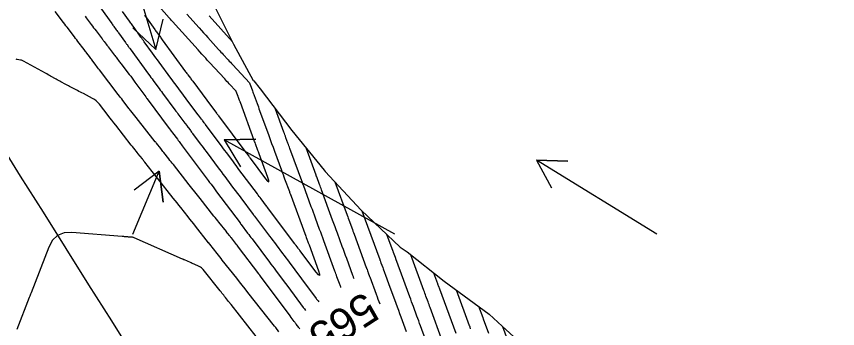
# Model space of a CAD drawing. Extents: x 954385 to 988206, y 1868364 to 1924553.
# Drawn here: x 957284.9 to 957441.7, y 1920650.9 to 1920710.5 of the extents above; entities that cross this region are included whole.
import ezdxf

# ---------------------------------------------------------------- set-up
doc = ezdxf.new("R2010")
doc.units = 0
for name, color, linetype in [('Default', 7, 'Continuous'), ('Ex_Contour Labels', 7, 'Continuous'), ('Ex_Major Contours', 7, 'Continuous'), ('Ex_Minor Contours', 7, 'Continuous'), ('Perimeter', 7, 'Continuous'), ('Slopes', 7, 'Continuous')]:
    doc.layers.add(name, color=color, linetype=linetype)

msp = doc.modelspace()

# ---------------------------------------------------------------- linework, layer by layer
at = {"layer": 'Default'}
msp.add_arc((966995.78, 1926764.93), 11459.16, 211.460692, 214.075074, dxfattribs=at)
at = {"layer": 'Ex_Major Contours'}
for points in [[(957300.93, 1920712.2), (957303.09, 1920709.21), (957303.2, 1920709.06), (957303.31, 1920708.9), (957303.42, 1920708.75), (957303.53, 1920708.6), (957303.97, 1920707.99), (957304.08, 1920707.84), (957304.19, 1920707.69), (957304.3, 1920707.53), (957304.41, 1920707.38), (957305.73, 1920705.56), (957305.8, 1920705.46), (957305.87, 1920705.36), (957305.94, 1920705.25), (957306.02, 1920705.15), (957306.31, 1920704.75), (957306.38, 1920704.65), (957306.45, 1920704.55), (957306.53, 1920704.45), (957306.6, 1920704.35), (957310.14, 1920699.5), (957310.36, 1920699.19), (957310.58, 1920698.89), (957310.8, 1920698.59), (957311.02, 1920698.29), (957311.91, 1920697.08), (957312.13, 1920696.78), (957312.35, 1920696.48), (957312.57, 1920696.18), (957312.79, 1920695.88), (957315.17, 1920692.69), (957315.36, 1920692.43), (957315.56, 1920692.18), (957315.75, 1920691.92), (957315.94, 1920691.66), (957317.08, 1920690.14), (957317.09, 1920690.12), (957317.12, 1920690.08), (957317.13, 1920690.07), (957317.42, 1920689.68), (957317.47, 1920689.62), (957317.52, 1920689.55), (957317.57, 1920689.48), (957317.62, 1920689.42), (957318.13, 1920688.73), (957318.23, 1920688.6), (957318.33, 1920688.46), (957318.43, 1920688.32), (957318.54, 1920688.19), (957320, 1920686.22), (957320.28, 1920685.85), (957320.56, 1920685.48), (957320.84, 1920685.1), (957321.11, 1920684.73), (957323.63, 1920681.36), (957323.98, 1920680.9), (957324.32, 1920680.44), (957324.66, 1920679.99), (957325, 1920679.53), (957326.37, 1920677.7), (957326.71, 1920677.25), (957327.05, 1920676.79), (957327.4, 1920676.33), (957327.74, 1920675.88), (957330.11, 1920672.7), (957330.14, 1920672.67), (957330.16, 1920672.64), (957330.21, 1920672.58), (957330.23, 1920672.55), (957330.25, 1920672.52), (957330.32, 1920672.44), (957330.34, 1920672.41), (957333.22, 1920668.57), (957333.53, 1920668.16), (957333.84, 1920667.75), (957334.15, 1920667.33), (957334.46, 1920666.92), (957335.7, 1920665.26), (957336.01, 1920664.85), (957336.32, 1920664.44), (957336.63, 1920664.02), (957336.94, 1920663.61), (957340.4, 1920658.98), (957341.04, 1920658.13), (957342.14, 1920656.65), (957342.22, 1920656.54), (957342.31, 1920656.43), (957342.39, 1920656.32), (957342.48, 1920656.2), (957342.61, 1920656.03)], [(957326.15, 1920705.7), (957321.7, 1920710.64)], [(957346.85, 1920658.78), (957346.81, 1920658.9), (957346.75, 1920659.05), (957346.69, 1920659.2), (957346.64, 1920659.35), (957346.58, 1920659.51), (957346.1, 1920660.82), (957346, 1920661.09), (957345.91, 1920661.36), (957345.81, 1920661.63), (957345.71, 1920661.9), (957343.59, 1920667.69), (957343.39, 1920668.23), (957343.19, 1920668.78), (957342.99, 1920669.32), (957342.79, 1920669.86), (957341.99, 1920672.02), (957341.8, 1920672.57), (957341.6, 1920673.11), (957341.4, 1920673.65), (957341.2, 1920674.19), (957339.69, 1920678.3), (957339.66, 1920678.35), (957339.62, 1920678.47), (957339.6, 1920678.52), (957339.57, 1920678.6), (957339.56, 1920678.65), (957337.11, 1920685.31), (957337.02, 1920685.57), (957336.92, 1920685.83), (957336.83, 1920686.09), (957336.73, 1920686.35), (957336.35, 1920687.38), (957336.26, 1920687.64), (957336.16, 1920687.9), (957336.07, 1920688.15), (957335.97, 1920688.41), (957334.36, 1920692.85)], [(957366.27, 1920648.44), (957363.88, 1920654.94), (957363.78, 1920655.22), (957363.68, 1920655.49), (957363.58, 1920655.76), (957363.48, 1920656.03), (957363.08, 1920657.12), (957362.98, 1920657.39), (957362.88, 1920657.67), (957362.78, 1920657.94), (957362.68, 1920658.21), (957360.18, 1920665.02)]]:
    msp.add_lwpolyline(points, dxfattribs=at)
at = {"layer": 'Ex_Minor Contours'}
for points in [[(957309.36, 1920710.74), (957309.54, 1920710.5), (957309.63, 1920710.37), (957309.72, 1920710.25), (957311.3, 1920708.06), (957311.42, 1920707.9), (957311.54, 1920707.73), (957311.66, 1920707.57), (957311.78, 1920707.4), (957312.26, 1920706.75), (957312.38, 1920706.58), (957312.5, 1920706.42), (957312.62, 1920706.25), (957312.74, 1920706.09), (957317.21, 1920699.97), (957317.32, 1920699.81), (957317.43, 1920699.66), (957317.54, 1920699.51), (957317.65, 1920699.36), (957318.11, 1920698.76), (957318.22, 1920698.6), (957318.33, 1920698.45), (957318.44, 1920698.3), (957318.56, 1920698.15), (957322.16, 1920693.32), (957322.18, 1920693.3), (957323.12, 1920692.05), (957323.18, 1920691.97), (957323.24, 1920691.89), (957323.36, 1920691.73), (957323.42, 1920691.65), (957323.47, 1920691.57), (957328.72, 1920684.54), (957328.86, 1920684.36), (957328.99, 1920684.18), (957329.26, 1920683.82), (957329.33, 1920683.73), (957329.39, 1920683.64), (957329.46, 1920683.55), (957329.53, 1920683.46), (957332.45, 1920679.55), (957332.86, 1920679.06), (957333.07, 1920678.93), (957333.08, 1920679.18), (957332.89, 1920679.79), (957331.24, 1920684.27), (957331.17, 1920684.48), (957331.09, 1920684.7), (957331.01, 1920684.92), (957330.93, 1920685.13), (957330.61, 1920686), (957330.53, 1920686.22), (957330.45, 1920686.43), (957330.37, 1920686.65), (957330.3, 1920686.87), (957327.66, 1920694.08), (957327.63, 1920694.18), (957327.59, 1920694.27), (957327.56, 1920694.37), (957327.52, 1920694.47), (957327.37, 1920694.85), (957327.34, 1920694.95), (957327.3, 1920695.04), (957327.26, 1920695.14), (957327.23, 1920695.24), (957326.87, 1920696.2), (957326.87, 1920696.21), (957326.87, 1920696.21), (957326.87, 1920696.22), (957326.86, 1920696.22), (957326.84, 1920696.24), (957326.83, 1920696.26), (957325.53, 1920697.66), (957325.32, 1920697.9), (957325.1, 1920698.13), (957324.88, 1920698.37), (957324.67, 1920698.6), (957321.77, 1920701.75), (957321.58, 1920701.95), (957321.4, 1920702.15), (957321.22, 1920702.35), (957321.04, 1920702.55), (957320.31, 1920703.36), (957319.94, 1920703.76), (957319.58, 1920704.17), (957314.73, 1920709.54), (957314.68, 1920709.6), (957314.62, 1920709.66), (957314.57, 1920709.72), (957314.52, 1920709.78), (957314.31, 1920710.02), (957314.2, 1920710.14), (957314.09, 1920710.25), (957312.15, 1920712.43)], [(957339.01, 1920650.86), (957338.9, 1920651.01), (957338.79, 1920651.15), (957338.33, 1920651.77), (957338.23, 1920651.9), (957338.13, 1920652.03), (957338.04, 1920652.16), (957337.94, 1920652.28), (957337.38, 1920653.03), (957337.25, 1920653.2), (957337.21, 1920653.26), (957331.62, 1920660.74), (957331.34, 1920661.11), (957331.29, 1920661.17), (957331.25, 1920661.23), (957331.2, 1920661.3), (957331.15, 1920661.36), (957327.32, 1920666.47), (957327.17, 1920666.67), (957327.02, 1920666.86), (957326.87, 1920667.06), (957326.71, 1920667.25), (957325.94, 1920668.23), (957325.86, 1920668.32), (957325.79, 1920668.42), (957325.71, 1920668.52), (957325.63, 1920668.61), (957325.21, 1920669.15), (957325.15, 1920669.22), (957325.02, 1920669.39), (957324.98, 1920669.44), (957323.57, 1920671.22), (957323.33, 1920671.52), (957323.09, 1920671.82), (957322.86, 1920672.12), (957322.62, 1920672.42), (957319.98, 1920675.75), (957319.46, 1920676.41), (957318.94, 1920677.06), (957318.42, 1920677.72), (957317.91, 1920678.37), (957314.86, 1920682.24), (957314.65, 1920682.51), (957314.43, 1920682.78), (957314.22, 1920683.05), (957314.01, 1920683.32), (957313.02, 1920684.58), (957312.87, 1920684.76), (957312.73, 1920684.94), (957312.59, 1920685.12), (957312.45, 1920685.3), (957311.62, 1920686.35), (957311.57, 1920686.42), (957311.49, 1920686.52), (957311.48, 1920686.52), (957311.45, 1920686.57), (957311.43, 1920686.58), (957311.42, 1920686.6), (957307.78, 1920691.21), (957307.52, 1920691.53), (957307.27, 1920691.85), (957306.76, 1920692.5), (957306.64, 1920692.66), (957306.51, 1920692.82), (957306.39, 1920692.98), (957306.26, 1920693.14), (957305.22, 1920694.5), (957305.01, 1920694.78), (957304.79, 1920695.06), (957304.58, 1920695.34), (957304.36, 1920695.62), (957300.75, 1920700.34), (957300.58, 1920700.56), (957300.41, 1920700.78), (957300.25, 1920700.99), (957300.08, 1920701.21), (957299.34, 1920702.2), (957299.21, 1920702.36), (957299.08, 1920702.53), (957298.96, 1920702.7), (957298.83, 1920702.86), (957298.33, 1920703.53), (957298.2, 1920703.7), (957298.07, 1920703.87), (957297.95, 1920704.03), (957297.82, 1920704.2), (957296.66, 1920705.73), (957296.44, 1920706.04), (957296.21, 1920706.34), (957295.98, 1920706.64), (957295.75, 1920706.95), (957294.83, 1920708.16), (957294.6, 1920708.46), (957294.37, 1920708.77), (957294.14, 1920709.07), (957293.91, 1920709.37), (957292.31, 1920711.48)], [(957298, 1920710.57), (957298.23, 1920710.26), (957299.19, 1920708.99), (957299.42, 1920708.69), (957299.65, 1920708.39), (957299.88, 1920708.09), (957300.1, 1920707.79), (957301.27, 1920706.24), (957301.37, 1920706.12), (957301.47, 1920705.99), (957301.56, 1920705.86), (957301.66, 1920705.73), (957302.05, 1920705.21), (957302.15, 1920705.08), (957302.25, 1920704.96), (957302.34, 1920704.83), (957302.44, 1920704.7), (957303.56, 1920703.21), (957303.68, 1920703.05), (957303.8, 1920702.9), (957303.93, 1920702.74), (957304.05, 1920702.58), (957304.53, 1920701.95), (957304.65, 1920701.79), (957304.77, 1920701.63), (957304.89, 1920701.47), (957305.02, 1920701.31), (957306.44, 1920699.46), (957306.72, 1920699.1), (957306.99, 1920698.73), (957307.26, 1920698.36), (957307.53, 1920698), (957309.58, 1920695.19), (957309.67, 1920695.07), (957309.76, 1920694.94), (957309.78, 1920694.91), (957309.81, 1920694.88), (957309.83, 1920694.85), (957309.85, 1920694.82), (957314.07, 1920689.16), (957314.17, 1920689.04), (957314.26, 1920688.91), (957314.53, 1920688.55), (957314.55, 1920688.53), (957314.58, 1920688.48), (957314.6, 1920688.46), (957314.69, 1920688.34), (957314.71, 1920688.31), (957315.64, 1920687.07), (957315.72, 1920686.97), (957315.79, 1920686.86), (957315.87, 1920686.76), (957315.95, 1920686.66), (957316.25, 1920686.24), (957316.41, 1920686.04), (957316.56, 1920685.83), (957321.51, 1920679.21), (957321.64, 1920679.03), (957321.78, 1920678.85), (957321.91, 1920678.67), (957322.05, 1920678.49), (957322.59, 1920677.77), (957322.72, 1920677.59), (957322.86, 1920677.41), (957322.99, 1920677.23), (957323.13, 1920677.05), (957327.59, 1920671.09), (957327.61, 1920671.06), (957327.64, 1920671.02), (957327.65, 1920671), (957327.76, 1920670.86), (957327.81, 1920670.79), (957329.04, 1920669.15), (957329.25, 1920668.87), (957329.46, 1920668.59), (957329.68, 1920668.31), (957329.89, 1920668.03), (957333.2, 1920663.61), (957333.49, 1920663.22), (957333.78, 1920662.83), (957334.08, 1920662.45), (957334.37, 1920662.06), (957335.82, 1920660.11), (957336.7, 1920658.94), (957339.67, 1920654.96), (957339.72, 1920654.89), (957339.77, 1920654.82), (957339.82, 1920654.76), (957339.87, 1920654.69), (957340.1, 1920654.39)], [(957317.45, 1920710.94), (957319.79, 1920708.34), (957320.21, 1920707.88), (957320.62, 1920707.42), (957321.04, 1920706.96), (957321.45, 1920706.5), (957323.49, 1920704.24), (957323.72, 1920703.99), (957323.94, 1920703.74), (957324.17, 1920703.5), (957324.39, 1920703.25), (957325.3, 1920702.27), (957325.52, 1920702.02), (957325.75, 1920701.78), (957325.98, 1920701.53), (957326.2, 1920701.29), (957329.38, 1920697.85), (957329.38, 1920697.84), (957329.39, 1920697.83), (957329.46, 1920697.64), (957329.47, 1920697.61), (957329.48, 1920697.57), (957329.49, 1920697.54), (957329.51, 1920697.51), (957329.97, 1920696.3), (957330.05, 1920696.08), (957330.13, 1920695.87), (957330.21, 1920695.65), (957330.29, 1920695.44), (957330.85, 1920693.9), (957330.97, 1920693.57), (957331.09, 1920693.24), (957331.21, 1920692.91), (957331.33, 1920692.58), (957333.08, 1920687.79), (957333.35, 1920687.04), (957333.63, 1920686.3), (957333.9, 1920685.55), (957334.17, 1920684.81), (957335.5, 1920681.18), (957335.66, 1920680.76), (957335.81, 1920680.35), (957335.96, 1920679.93), (957336.11, 1920679.52), (957337.01, 1920677.07), (957337.03, 1920677.02), (957337.05, 1920676.96), (957337.1, 1920676.81), (957337.11, 1920676.79), (957337.14, 1920676.72), (957340.13, 1920668.59), (957340.24, 1920668.31), (957340.34, 1920668.02), (957340.55, 1920667.46), (957340.6, 1920667.31), (957340.65, 1920667.17), (957340.7, 1920667.03), (957340.76, 1920666.89), (957342.57, 1920661.94), (957342.77, 1920661.29), (957342.77, 1920661.03), (957342.54, 1920661.16), (957342.11, 1920661.69), (957339.02, 1920665.82), (957338.94, 1920665.93), (957338.86, 1920666.04), (957338.78, 1920666.15), (957338.69, 1920666.26), (957338.29, 1920666.8), (957338.13, 1920667.01), (957338.05, 1920667.12), (957332.86, 1920674.02), (957332.82, 1920674.08), (957332.8, 1920674.1), (957332.71, 1920674.23), (957332.69, 1920674.25), (957332.68, 1920674.27), (957332.66, 1920674.3), (957332.64, 1920674.32), (957331.61, 1920675.7), (957331.43, 1920675.94), (957331.25, 1920676.17), (957331.07, 1920676.41), (957330.9, 1920676.65), (957327.39, 1920681.32), (957327.12, 1920681.68), (957326.86, 1920682.04), (957326.59, 1920682.4), (957326.32, 1920682.76), (957325.25, 1920684.2), (957324.98, 1920684.56), (957324.71, 1920684.92), (957324.44, 1920685.28), (957324.17, 1920685.64), (957321.01, 1920689.88), (957320.94, 1920689.97), (957320.87, 1920690.06), (957320.81, 1920690.14), (957320.74, 1920690.23), (957320.48, 1920690.58), (957320.41, 1920690.67), (957320.35, 1920690.76), (957320.28, 1920690.85), (957320.22, 1920690.93), (957319.65, 1920691.69), (957319.64, 1920691.7), (957319.62, 1920691.73), (957317.46, 1920694.63), (957317.2, 1920694.97), (957316.94, 1920695.32), (957316.69, 1920695.66), (957316.43, 1920696), (957315.4, 1920697.38), (957315.15, 1920697.72), (957314.89, 1920698.07), (957314.64, 1920698.42), (957314.38, 1920698.76), (957312.18, 1920701.78), (957311.86, 1920702.22), (957311.54, 1920702.65), (957311.22, 1920703.09), (957310.91, 1920703.53), (957309.31, 1920705.71), (957309.15, 1920705.93), (957309, 1920706.14), (957308.84, 1920706.36), (957308.68, 1920706.57), (957308.01, 1920707.51), (957307.88, 1920707.69), (957307.75, 1920707.86), (957307.62, 1920708.04), (957307.5, 1920708.22), (957306.99, 1920708.92), (957306.86, 1920709.1), (957306.73, 1920709.28), (957306.6, 1920709.45), (957306.48, 1920709.63), (957305.14, 1920711.48)], [(957335.03, 1920650.32), (957334.4, 1920651.12), (957334.24, 1920651.32), (957334.2, 1920651.37), (957329.1, 1920657.84), (957328.56, 1920658.52), (957328.02, 1920659.2), (957327.49, 1920659.88), (957326.95, 1920660.55), (957324.21, 1920664.01), (957323.97, 1920664.31), (957323.73, 1920664.62), (957323.49, 1920664.92), (957323.24, 1920665.23), (957321.82, 1920667.03), (957321.76, 1920667.1), (957321.61, 1920667.28), (957321.59, 1920667.32), (957319.11, 1920670.45), (957318.75, 1920670.9), (957318.4, 1920671.34), (957318.04, 1920671.79), (957317.69, 1920672.24), (957316.27, 1920674.03), (957315.91, 1920674.48), (957315.56, 1920674.93), (957315.2, 1920675.38), (957314.85, 1920675.83), (957311.84, 1920679.64), (957311.59, 1920679.96), (957311.34, 1920680.28), (957311.09, 1920680.59), (957310.84, 1920680.91), (957309.42, 1920682.71), (957309.38, 1920682.76), (957309.34, 1920682.81), (957309.3, 1920682.86), (957309.26, 1920682.91), (957309.07, 1920683.16), (957308.99, 1920683.26), (957308.95, 1920683.31), (957308.11, 1920684.38), (957308.09, 1920684.4), (957308.06, 1920684.44), (957308.05, 1920684.44), (957308.04, 1920684.46), (957308.04, 1920684.46), (957307.32, 1920685.37), (957307.08, 1920685.68), (957306.84, 1920685.98), (957303.86, 1920689.76), (957303.49, 1920690.23), (957303.13, 1920690.7), (957302.76, 1920691.17), (957302.39, 1920691.64), (957300.74, 1920693.8), (957300.46, 1920694.12), (957300.15, 1920694.42), (957299.81, 1920694.67), (957299.44, 1920694.89), (957297.69, 1920695.79), (957297.4, 1920695.94), (957297.11, 1920696.09), (957296.82, 1920696.23), (957296.54, 1920696.38), (957295.29, 1920697.03), (957295.05, 1920697.15), (957294.82, 1920697.28), (957294.58, 1920697.4), (957294.35, 1920697.53), (957293.41, 1920698.05), (957293.18, 1920698.17), (957292.94, 1920698.3), (957292.71, 1920698.43), (957292.48, 1920698.56), (957291.44, 1920699.13), (957291.19, 1920699.27), (957290.94, 1920699.41), (957290.69, 1920699.55), (957290.44, 1920699.69), (957286.23, 1920702.02), (957286.11, 1920702.08), (957285.98, 1920702.13), (957285.85, 1920702.17), (957285.71, 1920702.2), (957285.04, 1920702.32), (957284.96, 1920702.33), (957284.89, 1920702.35)], [(957349.37, 1920660.43), (957349.32, 1920660.57), (957349.27, 1920660.69), (957349.23, 1920660.81), (957349.19, 1920660.92), (957349.14, 1920661.04), (957347.95, 1920664.29), (957347.74, 1920664.87), (957347.53, 1920665.45), (957347.32, 1920666.04), (957347.1, 1920666.62), (957346.18, 1920669.15), (957345.95, 1920669.76), (957345.73, 1920670.38), (957345.5, 1920670.99), (957345.27, 1920671.61), (957343.14, 1920677.4), (957343.05, 1920677.65), (957342.96, 1920677.91), (957342.86, 1920678.16), (957342.77, 1920678.41), (957342.23, 1920679.88), (957342.21, 1920679.93), (957342.19, 1920679.99), (957342.13, 1920680.16), (957342.1, 1920680.22), (957342.1, 1920680.23), (957340.19, 1920685.43)], [(957345.71, 1920678.92), (957348.04, 1920672.59), (957348.15, 1920672.28), (957348.26, 1920671.98), (957348.37, 1920671.68), (957348.49, 1920671.37), (957348.93, 1920670.16), (957349.04, 1920669.85), (957349.15, 1920669.55), (957349.26, 1920669.25), (957349.38, 1920668.94), (957351.7, 1920662.58), (957351.73, 1920662.5), (957351.76, 1920662.41), (957351.8, 1920662.33), (957351.83, 1920662.24), (957351.95, 1920661.9), (957351.98, 1920661.82), (957352.01, 1920661.73), (957352.04, 1920661.65), (957352.08, 1920661.56), (957352.32, 1920660.89), (957352.36, 1920660.8), (957353.58, 1920657.47), (957353.75, 1920657.01), (957353.92, 1920656.55), (957354.09, 1920656.08), (957354.26, 1920655.62)], [(957350.86, 1920673.42), (957354.26, 1920664.12), (957354.3, 1920664.01), (957354.34, 1920663.91), (957354.43, 1920663.66), (957354.47, 1920663.55), (957354.49, 1920663.5), (957354.82, 1920662.59), (957354.92, 1920662.34), (957355.62, 1920660.43), (957355.75, 1920660.07), (957355.88, 1920659.71), (957356.01, 1920659.35), (957356.14, 1920658.99), (957357.33, 1920655.75), (957357.57, 1920655.1), (957357.81, 1920654.45), (957358.05, 1920653.8), (957358.29, 1920653.15), (957359.33, 1920650.34)], [(957330.7, 1920649.38), (957325.88, 1920655.5), (957325.38, 1920656.12), (957324.82, 1920656.85), (957324.73, 1920656.95), (957324.64, 1920657.06), (957324.56, 1920657.17), (957324.47, 1920657.28), (957324.13, 1920657.71), (957324.04, 1920657.82), (957323.96, 1920657.93), (957323.87, 1920658.04), (957323.79, 1920658.14), (957320.55, 1920662.22), (957320.39, 1920662.4), (957320.22, 1920662.55), (957320.02, 1920662.68), (957319.81, 1920662.79), (957318.85, 1920663.21), (957318.67, 1920663.29), (957318.48, 1920663.38), (957318.29, 1920663.46), (957318.11, 1920663.54), (957316.99, 1920664.03), (957316.89, 1920664.07), (957316.72, 1920664.15), (957316.66, 1920664.18), (957316.6, 1920664.2), (957307.38, 1920668.26), (957307.28, 1920668.3), (957307.17, 1920668.33), (957307.06, 1920668.35), (957306.95, 1920668.36), (957306.51, 1920668.4), (957306.4, 1920668.41), (957306.29, 1920668.41), (957306.17, 1920668.42), (957306.06, 1920668.43), (957305.56, 1920668.47), (957305.44, 1920668.48), (957305.31, 1920668.49), (957305.19, 1920668.5), (957305.07, 1920668.51), (957295.51, 1920669.29), (957294.01, 1920669.21), (957292.77, 1920668.72), (957291.79, 1920667.82), (957291.07, 1920666.49), (957287.71, 1920657.74), (957287.62, 1920657.52), (957287.54, 1920657.31), (957287.45, 1920657.09), (957287.37, 1920656.87), (957284.99, 1920650.74)], [(957363.7, 1920646.93), (957362.04, 1920651.45), (957361.87, 1920651.91), (957361.7, 1920652.37), (957361.53, 1920652.83), (957361.36, 1920653.29), (957360.68, 1920655.14), (957360.51, 1920655.6), (957360.35, 1920656.06), (957360.18, 1920656.52), (957360.01, 1920656.98), (957357.96, 1920662.54), (957357.84, 1920662.87), (957357.72, 1920663.2), (957357.42, 1920664.03), (957357.24, 1920664.52), (957356.9, 1920665.44), (957356.87, 1920665.51), (957356.83, 1920665.64), (957356.82, 1920665.65), (957355.64, 1920668.89)], [(957368.84, 1920649.95), (957365.72, 1920658.44), (957365.66, 1920658.61), (957365.6, 1920658.77), (957365.47, 1920659.11), (957365.44, 1920659.19), (957365.41, 1920659.27), (957365.38, 1920659.35), (957365.35, 1920659.44), (957364.59, 1920661.51)], [(957371.61, 1920650.9), (957371.51, 1920651.18), (957371.49, 1920651.25), (957371.46, 1920651.32), (957371.43, 1920651.39), (957371.41, 1920651.46), (957368.92, 1920658.24)], [(957375.08, 1920649.99), (957374.07, 1920652.71), (957374.04, 1920652.8), (957374, 1920652.91), (957373.98, 1920652.98), (957373.18, 1920655.13)], [(957377.71, 1920651.34), (957379.92, 1920645.27)]]:
    msp.add_lwpolyline(points, dxfattribs=at)
at = {"layer": 'Perimeter'}
msp.add_lwpolyline([(957321.88, 1920714.2), (957326.37, 1920705.27), (957330.11, 1920698.3), (957330.2, 1920698.26), (957331.42, 1920696.68), (957337.51, 1920688.75), (957343.63, 1920681.18), (957343.82, 1920680.95), (957350.73, 1920673.54), (957358.19, 1920666.47), (957359.5, 1920665.55), (957366.53, 1920659.98), (957375.17, 1920653.68), (957377.65, 1920651.39), (957382.74, 1920646.71)], dxfattribs=at)
at = {"layer": 'Slopes'}
for points in [[(957307.13, 1920718.93), (957311.5, 1920704.2), (957307.14, 1920708.33), (957311.5, 1920704.2), (957312.9, 1920710.03)], [(957357.13, 1920668.93), (957324.58, 1920686.97), (957330.58, 1920687.08), (957324.58, 1920686.97), (957327.67, 1920681.83)], [(957407.13, 1920668.93), (957384.17, 1920683.08), (957390.17, 1920682.91), (957384.17, 1920683.08), (957387.02, 1920677.8)], [(957307.13, 1920668.93), (957312.14, 1920681.01), (957312.92, 1920675.06), (957312.14, 1920681.01), (957307.38, 1920677.36)]]:
    msp.add_lwpolyline(points, dxfattribs=at)

# ---------------------------------------------------------------- texts
at = {"layer": 'Ex_Contour Labels'}
msp.add_text('565', height=6, rotation=213.0663, dxfattribs=at).set_placement((957351.35, 1920658.13))

doc.saveas('drawing.dxf')
